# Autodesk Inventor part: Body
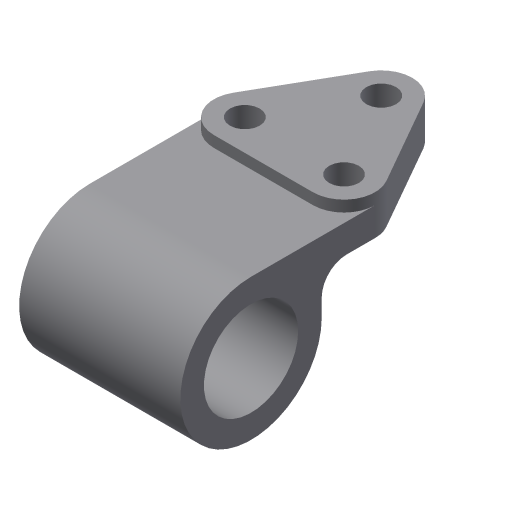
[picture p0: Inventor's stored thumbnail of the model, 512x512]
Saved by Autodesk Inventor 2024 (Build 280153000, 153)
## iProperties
Created: 2010-03
Part Number: Body
Document SubType Name: Modeling
Designer: bhakira
Density: 1 g/cm^3
Material: Generic
Appearance: Default
Author: bhakira
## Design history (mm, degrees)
sketch "Sketch1"
  geometry: L1 (10.853, 41.202)-(30.853, 6.202); L2 (-10.853, 41.202)-(-30.853, 6.202); L3 (-20, -12.5)-(20, -12.5); C1 r 6 at (0, 35); A1 r 12.5 centre (0, 35) between (10.853, 41.202) and (-10.853, 41.202); A2 r 12.5 centre (-20, 0) between (-30.853, 6.202) and (-20, -12.5); A3 r 12.5 centre (20, 0) between (20, -12.5) and (30.853, 6.202); 1 further point
  constraints: 6 end point, 6 point on circle, 6 tangent, 4 centre point, 3 horizontal alignment, 2 equal radius, 1 coincident, 1 vertical alignment, 1 other
  dimensions: "d25" = 35 vertical distance of A1.centre A2.centre; "d27" = 12.5 radius of A1; "d28" = 40 distance of A3.centre A2.centre; "d29" = 20 horizontal distance of A3.centre A1.centre
extrude "Extrusion1" new body sketch "Sketch1" distance "d6" = 16; taper "d7" = 0 deg
workplane "Work Plane2"
workplane "Work Plane3"
sketch "Sketch2"
  geometry: L1 (0, 11.5)-(0, 0); L2 (-12.5, 16)-(6.202, 16) reference; L3 (-50, 11.5)-(0, 11.5); L4 (0, 0)-(-21.5, 0); L5 (-21.5, -17)-(-21.5, 0); L6 (-12.5, 0)-(-12.5, 16) reference; C1 r 19 at (-50, -17); A1 r 28.5 centre (-50, -17) between (-50, 11.5) and (-21.5, -17)
  constraints: 8 end point, 2 centre point, 2 horizontal, 2 point on circle, 2 tangent, 1 coincident, 1 perpendicular, 1 vertical
  dimensions: "d9" = 38 diameter of C1; "d10" = 57 diameter of A1; "d11" = 50 distance from line of L1 C1.centre; "d12" = 33 distance from line of C1.centre L2
extrude "Extrusion2" join sketch "Sketch2" stored distance "d14" = 63.5; taper "d15" = 0 deg
sketch "Sketch3"
  geometry: C1 r 6 at (20, 0) reference; C2 r 6 at (-20, 0) reference; C3 r 6 at (0, 35); 1 further point
  constraints: 1 centre point
extrude "Extrusion3" cut sketch "Sketch3" distance "d16" = 63.5; taper "d17" = 0 deg
hole "Hole1" diameter "d32" = 12; stored, may be unused: countersink angle "d36" = 90 deg, drill point angle "d38" = 118 deg; dims "d33" = 6, "d34" = 4, "d35" = 2082.8, "d37" = 8, "d39" = 10, "d40" = 10
fillet "Fillet1" dims "d42" = 10
body "Solid1"
node "Sketch4"
